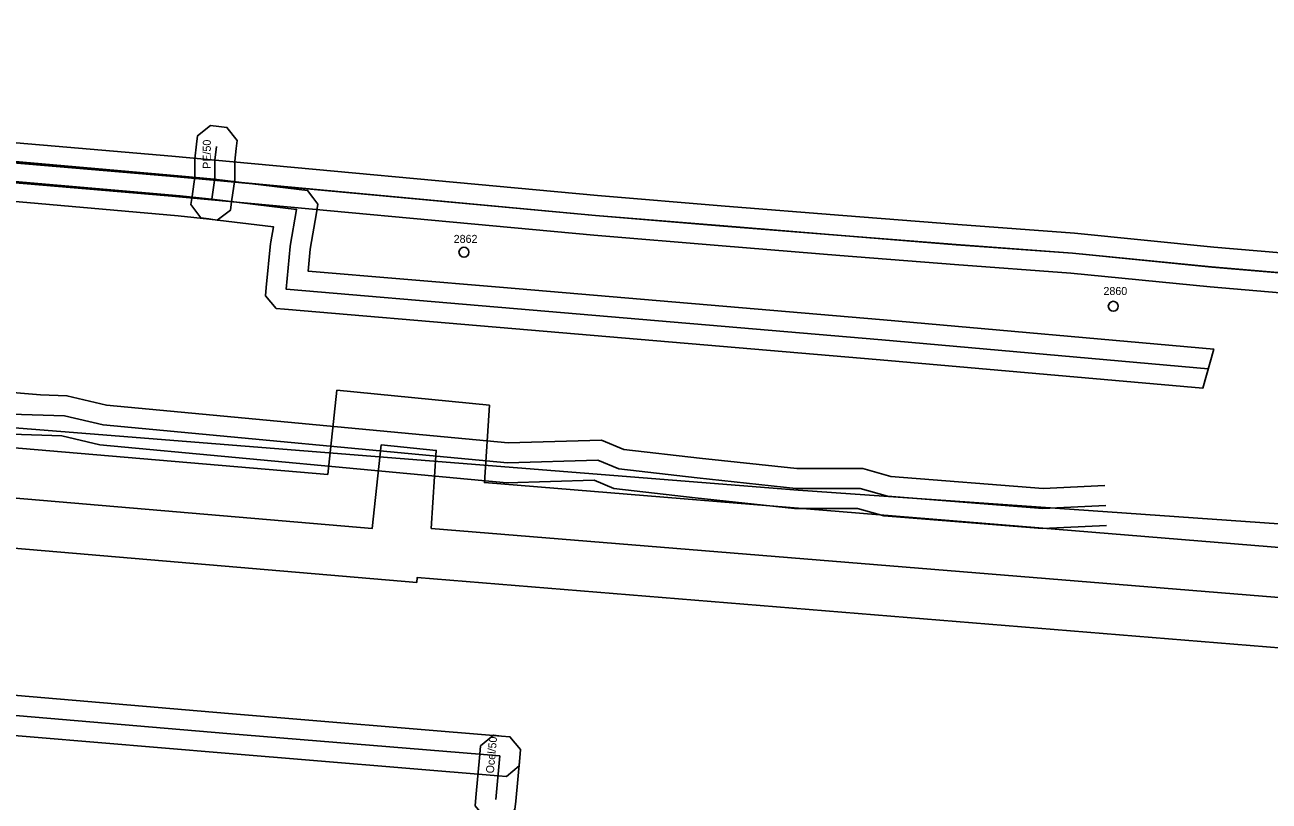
# Model space of a CAD drawing. Extents: x -762993 to -761845, y -975230 to -974501.
# Drawn here: x -762159.8 to -762097.6, y -975032.9 to -974994.1 of the extents above; entities that cross this region are included whole.
import ezdxf

# ---------------------------------------------------------------- set-up
doc = ezdxf.new("R2010")
doc.units = 0
for name, color, linetype in [('IS_CETIN_OP', 7, 'Continuous'), ('IS_CETIN_podzem metalika zam', 7, 'Continuous'), ('IS_CETIN_podzem optika zam', 7, 'Continuous'), ('IS_CETIN_podzem out of order', 7, 'Continuous'), ('IS_CEZ-T_parovod', 7, 'Continuous'), ('IS_CEZ-T_parovod OP', 7, 'Continuous'), ('IS_CRA_podzem telekomunikace', 7, 'Continuous'), ('IS_DPmUL_trakce anotace', 7, 'Continuous'), ('IS_DPmUL_trakce stozary', 7, 'Continuous'), ('IS_GASNET_plyn NTL anotace', 7, 'Continuous'), ('IS_GASNET_plyn NTL pripojky', 7, 'Continuous'), ('IS_GASNET_plyn NTL rad', 7, 'Continuous'), ('IS_GASNET_plyn OP', 7, 'Continuous')]:
    doc.layers.add(name, color=color, linetype=linetype)

msp = doc.modelspace()

# ---------------------------------------------------------------- linework, layer by layer
at = {"layer": 'IS_CETIN_OP'}
msp.add_line((-762187.135, -975010.105), (-762159.034, -975012.594), dxfattribs=at)
for points in [[(-762217.822, -974995.035), (-762216.005, -974995.184), (-762184.57, -974998.003), (-762178.542, -974998.433), (-762152.471, -975000.654), (-762131.203, -975002.624), (-762124.809, -975003.153), (-762118.93, -975003.623), (-762113.193, -975004.083), (-762107.364, -975004.514), (-762100.398, -975005.204), (-762087.589, -975006.295)], [(-762217.984, -974997.029), (-762216.175, -974997.176), (-762184.73, -974999.997), (-762178.698, -975000.427), (-762152.649, -975002.646), (-762131.377, -975004.616), (-762124.971, -975005.147), (-762119.09, -975005.617), (-762113.347, -975006.077), (-762107.536, -975006.506), (-762100.582, -975007.196), (-762087.759, -975008.287)], [(-762105.752, -975019.119), (-762108.956, -975019.272), (-762116.886, -975018.639), (-762118.209, -975018.27), (-762121.344, -975018.26), (-762126.32, -975017.734), (-762130.385, -975017.267), (-762131.367, -975016.856), (-762135.732, -975016.981), (-762156.063, -975015.079), (-762157.972, -975014.627), (-762160.485, -975014.551), (-762162.638, -975014.765), (-762176.145, -975013.475), (-762180.887, -975012.925), (-762183.621, -975012.711), (-762185.704, -975012.236), (-762187.743, -975012.352), (-762193.286, -975011.893), (-762194.38, -975011.419), (-762195.086, -975011.619)], [(-762105.848, -975017.121), (-762108.924, -975017.268), (-762116.534, -975016.661), (-762117.931, -975016.27), (-762121.236, -975016.26), (-762126.1, -975015.746), (-762129.875, -975015.313), (-762130.993, -975014.844), (-762135.668, -975014.979), (-762155.737, -975013.101), (-762157.708, -975012.633), (-762159.034, -975012.594)]]:
    msp.add_lwpolyline(points, dxfattribs=at)
at = {"layer": 'IS_CETIN_podzem metalika zam'}
msp.add_lwpolyline([(-762105.8, -975018.12), (-762108.94, -975018.27), (-762116.71, -975017.65), (-762118.07, -975017.27), (-762121.29, -975017.26), (-762126.21, -975016.74), (-762130.13, -975016.29), (-762131.18, -975015.85), (-762135.7, -975015.98), (-762155.9, -975014.09), (-762157.84, -975013.63), (-762160.52, -975013.55), (-762162.64, -975013.76), (-762176.04, -975012.48), (-762180.79, -975011.93), (-762183.47, -975011.72), (-762185.62, -975011.23), (-762187.73, -975011.35), (-762193.04, -975010.91), (-762194.31, -975010.36), (-762195.97, -975010.83)], dxfattribs=at)
at = {"layer": 'IS_CETIN_podzem optika zam'}
msp.add_lwpolyline([(-762217.903, -974996.032), (-762216.09, -974996.18), (-762184.65, -974999), (-762178.62, -974999.43), (-762152.56, -975001.65), (-762131.29, -975003.62), (-762124.89, -975004.15), (-762119.01, -975004.62), (-762113.27, -975005.08), (-762107.45, -975005.51), (-762100.49, -975006.2), (-762087.674, -975007.291)], dxfattribs=at)
at = {"layer": 'IS_CETIN_podzem out of order'}
msp.add_lwpolyline([(-762250.2, -975005.66), (-762210.15, -975010), (-762201.16, -975010.99), (-762121.16, -975017.35), (-762071.23, -975020.85), (-762043.47, -975023.41)], dxfattribs=at)
at = {"layer": 'IS_CEZ-T_parovod'}
msp.add_lwpolyline([(-761997.94, -975128.34), (-762040.63, -975080.79), (-762092.91, -975023.16), (-762093.78, -975023), (-762095.1, -975022.88), (-762139.5, -975019.26), (-762139.25, -975015.36), (-762142, -975015.09), (-762142.45, -975019.26), (-762189.8, -975015.24), (-762189.54, -975011.07), (-762194.02, -975010.75), (-762194.39, -975014.25), (-762239.28, -975010.18), (-762239.14, -975006.45), (-762242.94, -975006.24), (-762243.22, -975009.53), (-762252.6, -975008.69), (-762274.12, -975007.08), (-762277.86, -975004.82)], dxfattribs=at)
at = {"layer": 'IS_CEZ-T_parovod OP'}
for points in [[(-761996.08, -975126.67), (-762038.774, -975079.115), (-762091.626, -975020.854), (-762093.44, -975020.521), (-762094.885, -975020.389), (-762136.848, -975016.968), (-762136.601, -975013.108), (-762144.22, -975012.36), (-762144.673, -975016.562), (-762187.153, -975012.956), (-762186.891, -975008.753), (-762196.252, -975008.084), (-762196.617, -975011.538), (-762236.693, -975007.904), (-762236.55, -975004.089), (-762245.225, -975003.61), (-762245.498, -975006.816), (-762252.395, -975006.198), (-762273.338, -975004.632), (-762275.663, -975003.227)], [(-761999.8, -975130.01), (-762042.486, -975082.465), (-762094.187, -975025.473), (-762095.315, -975025.371), (-762140.2, -975021.711), (-762140.227, -975021.958), (-762192.447, -975017.524), (-762192.411, -975016.94), (-762241.867, -975012.456), (-762241.856, -975012.162), (-762252.805, -975011.182), (-762274.902, -975009.528), (-762278.275, -975007.49)]]:
    msp.add_lwpolyline(points, dxfattribs=at)
at = {"layer": 'IS_CRA_podzem telekomunikace'}
msp.add_lwpolyline([(-762257.583, -974994.102), (-762251.601, -974995.42), (-762242.483, -974996.496), (-762240.634, -974996.224), (-762237.225, -974994.464), (-762216.085, -974996.188), (-762184.646, -974998.998), (-762178.626, -974999.438), (-762152.565, -975001.658), (-762131.295, -975003.618), (-762124.896, -975004.158), (-762119.016, -975004.628), (-762113.267, -975005.088), (-762107.455, -975005.508), (-762100.504, -975006.198), (-762086.855, -975007.364)], dxfattribs=at)
at = {"layer": 'IS_DPmUL_trakce stozary'}
for centre in [(-762137.868, -975005.463), (-762105.418, -975008.163)]:
    msp.add_circle(centre, 0.25, dxfattribs=at)
at = {"layer": 'IS_GASNET_plyn NTL pripojky'}
for points in [[(-762150.47, -975002.81), (-762150.32, -975001.757), (-762150.32, -975000.871), (-762150.32, -975000.86), (-762150.24, -975000.17)], [(-762136.28, -975032.8), (-762136.08, -975030.63)]]:
    msp.add_lwpolyline(points, dxfattribs=at)
at = {"layer": 'IS_GASNET_plyn NTL rad'}
for points in [[(-762100.674, -975011.279), (-762116.99, -975009.84), (-762136.171, -975008.209), (-762146.75, -975007.31), (-762146.55, -975005.17), (-762146.547, -975005.156), (-762146.23, -975003.32), (-762150.47, -975002.81), (-762152.06, -975002.65), (-762164.37, -975001.57)], [(-762200.13, -975024.62), (-762197.953, -975024.87), (-762195.07, -975025.2), (-762193.3, -975025.13), (-762162.45, -975028.42), (-762149.72, -975029.5), (-762136.08, -975030.63)]]:
    msp.add_lwpolyline(points, dxfattribs=at)
at = {"layer": 'IS_GASNET_plyn OP'}
for points in [[(-762151.518, -975003.079), (-762151.46, -975002.669), (-762151.32, -975001.689), (-762151.32, -975000.802), (-762151.233, -975000.055), (-762151.185, -974999.643), (-762150.536, -974999.129), (-762150.125, -974999.177), (-762149.713, -974999.225), (-762149.199, -974999.874), (-762149.247, -975000.285), (-762149.32, -975000.918), (-762149.32, -975001.831), (-762149.48, -975002.951), (-762149.538, -975003.361), (-762150.201, -975003.858), (-762150.611, -975003.8), (-762151.021, -975003.742)], [(-762200.428, -975023.58), (-762200.016, -975023.627), (-762195.033, -975024.198), (-762193.267, -975024.128), (-762162.355, -975027.424), (-762149.636, -975028.503), (-762135.997, -975029.633), (-762135.584, -975029.667), (-762135.049, -975030.3), (-762135.083, -975030.713), (-762135.117, -975031.126), (-762135.75, -975031.661), (-762136.163, -975031.627), (-762149.804, -975030.497), (-762162.545, -975029.416), (-762193.333, -975026.132), (-762195.107, -975026.202), (-762200.244, -975025.613), (-762200.655, -975025.566), (-762201.17, -975024.918), (-762201.123, -975024.506), (-762201.076, -975024.095)], [(-762137.314, -975033.121), (-762137.276, -975032.708), (-762137.076, -975030.538), (-762137.038, -975030.125), (-762136.401, -975029.596), (-762135.988, -975029.634), (-762135.575, -975029.672), (-762135.046, -975030.309), (-762135.084, -975030.722), (-762135.284, -975032.892), (-762135.322, -975033.305), (-762135.959, -975033.834), (-762136.372, -975033.796), (-762136.785, -975033.758)]]:
    msp.add_lwpolyline(points, close=True, dxfattribs=at)
msp.add_lwpolyline([(-762164.273, -975000.575), (-762151.966, -975001.654), (-762150.36, -975001.816), (-762146.111, -975002.327), (-762145.684, -975002.378), (-762145.428, -975002.723), (-762145.172, -975003.067), (-762145.245, -975003.49), (-762145.558, -975005.305), (-762145.661, -975006.399), (-762136.086, -975007.213), (-762116.904, -975008.844), (-762100.401, -975010.299), (-762100.947, -975012.259), (-762117.076, -975010.836), (-762136.256, -975009.205), (-762146.835, -975008.306), (-762147.25, -975008.271), (-762147.517, -975007.951), (-762147.784, -975007.632), (-762147.746, -975007.217), (-762147.54, -975005.018), (-762147.526, -975004.95), (-762147.525, -975004.946), (-762147.395, -975004.187), (-762150.58, -975003.804), (-762152.154, -975003.646), (-762164.467, -975002.565)], dxfattribs=at)

# ---------------------------------------------------------------- texts
at = {"layer": 'IS_DPmUL_trakce anotace'}
for s, p in [('2862', (-762138.383, -975004.994)), ('2860', (-762105.911, -975007.599))]:
    msp.add_text(s, height=0.4, dxfattribs=at).set_placement(p)
at = {"layer": 'IS_GASNET_plyn NTL anotace'}
for s, rotation, p in [('PE/50', 90, (-762150.52, -975001.293)), ('Ocel/50', 84.73416, (-762136.38, -975031.515))]:
    msp.add_text(s, height=0.4, rotation=rotation, dxfattribs=at).set_placement(p)

doc.saveas('drawing.dxf')
